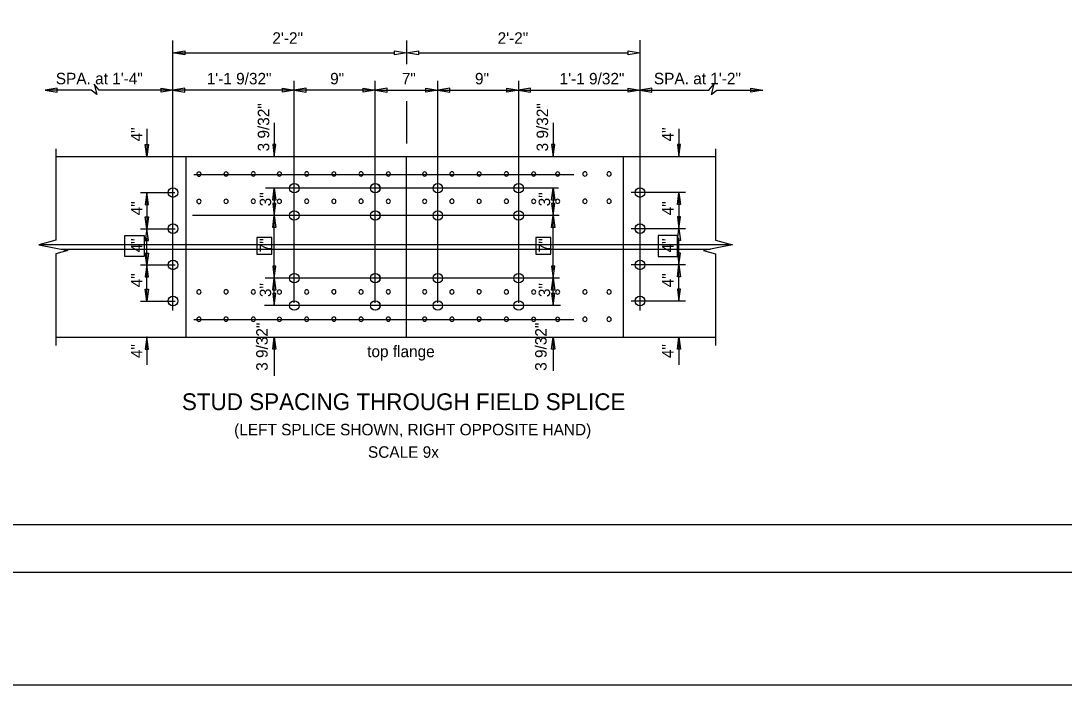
# Model space of a CAD drawing. Extents: x 4944 to 17449, y 3824 to 49087.
# Drawn here: x 13104 to 14149, y 32310 to 32976 of the extents above; entities that cross this region are included whole.
import ezdxf

# ---------------------------------------------------------------- set-up
doc = ezdxf.new("R2010")
doc.units = 0
for name, color, linetype in [('1', 7, 'Continuous'), ('2', 7, 'Continuous'), ('36_S_LINES', 7, 'Continuous'), ('37_S_TXT', 7, 'Continuous'), ('3A', 7, 'Continuous'), ('7', 7, 'Continuous'), ('BEAM', 7, 'Continuous'), ('DIM', 7, 'Continuous'), ('Level 14', 7, 'Continuous'), ('Level 25', 7, 'Continuous'), ('Level 35', 7, 'Continuous')]:
    doc.layers.add(name, color=color, linetype=linetype)

# ---------------------------------------------------------------- blocks, each defined once
blk = doc.blocks.new('4MH')
at = {"layer": 'Level 35'}
for radius, start, end in [(0.0945, 112.5426, 157.4574), (0.06, 112.5426, 157.4574), (0.06, 22.5426, 67.4574), (0.0945, 22.5426, 67.4574), (0.0945, 202.5426, 247.4574), (0.06, 202.5426, 247.4574), (0.06, 292.5426, 337.4574), (0.0945, 292.5426, 337.4574)]:
    blk.add_arc((0, 0), radius, start, end, dxfattribs=at)

msp = doc.modelspace()

# ---------------------------------------------------------------- linework, layer by layer
at = {"layer": '1'}
for centre, start, end in [((13282, 32822.2), 0, 180), ((13282, 32822.2), 180, 0), ((13309.2, 32822.3), 0, 180), ((13309.2, 32822.3), 180, 0), ((13336.5, 32822.4), 0, 180), ((13336.5, 32822.4), 180, 0), ((13362.7, 32822.3), 0, 180), ((13362.7, 32822.3), 180, 0), ((13390, 32822.4), 0, 180), ((13390, 32822.4), 180, 0), ((13417.2, 32822.3), 0, 180), ((13417.2, 32822.3), 180, 0), ((13444.5, 32822.4), 0, 180), ((13444.5, 32822.4), 180, 0), ((13471.8, 32822.3), 0, 180), ((13471.8, 32822.3), 180, 0), ((13508.2, 32822.3), 0, 180), ((13508.2, 32822.3), 180, 0), ((13535.5, 32822.4), 0, 180), ((13535.5, 32822.4), 180, 0), ((13562.8, 32822.3), 0, 180), ((13562.8, 32822.3), 180, 0), ((13590.1, 32822.4), 0, 180), ((13590.1, 32822.4), 180, 0), ((13617.4, 32822.3), 0, 180), ((13617.4, 32822.3), 180, 0), ((13641.5, 32822.3), 0, 180), ((13641.5, 32822.3), 180, 0), ((13668.8, 32822.4), 0, 180), ((13668.8, 32822.4), 180, 0), ((13693, 32822.4), 0, 180), ((13693, 32822.4), 180, 0), ((13282, 32794.8), 0, 180), ((13282, 32794.8), 180, 0), ((13309.2, 32794.9), 0, 180), ((13309.2, 32794.9), 180, 0), ((13336.5, 32795), 0, 180), ((13336.5, 32795), 180, 0), ((13362.7, 32794.9), 0, 180), ((13362.7, 32794.9), 180, 0), ((13390, 32795), 0, 180), ((13390, 32795), 180, 0), ((13417.2, 32794.9), 0, 180), ((13417.2, 32794.9), 180, 0), ((13444.5, 32795), 0, 180), ((13444.5, 32795), 180, 0), ((13471.8, 32794.9), 0, 180), ((13471.8, 32794.9), 180, 0), ((13508.2, 32794.9), 0, 180), ((13508.2, 32794.9), 180, 0), ((13535.5, 32795), 0, 180), ((13535.5, 32795), 180, 0), ((13562.8, 32794.9), 0, 180), ((13562.8, 32794.9), 180, 0), ((13590.1, 32795), 0, 180), ((13590.1, 32795), 180, 0), ((13617.4, 32794.9), 0, 180), ((13617.4, 32794.9), 180, 0), ((13641.5, 32794.9), 0, 180), ((13641.5, 32794.9), 180, 0), ((13668.8, 32795), 0, 180), ((13668.8, 32795), 180, 0), ((13693, 32795), 0, 180), ((13693, 32795), 180, 0), ((13282, 32704.1), 0, 180), ((13282, 32704.1), 180, 0), ((13309.2, 32704.2), 0, 180), ((13309.2, 32704.2), 180, 0), ((13336.5, 32704.1), 0, 180), ((13336.5, 32704.1), 180, 0), ((13362.7, 32704), 0, 180), ((13362.7, 32704), 180, 0), ((13390, 32704.1), 0, 180), ((13390, 32704.1), 180, 0), ((13417.2, 32704.2), 0, 180), ((13417.2, 32704.2), 180, 0), ((13444.5, 32704.1), 0, 180), ((13444.5, 32704.1), 180, 0), ((13471.8, 32704.2), 0, 180), ((13471.8, 32704.2), 180, 0), ((13508.2, 32704.2), 0, 180), ((13508.2, 32704.2), 180, 0), ((13535.5, 32704.1), 0, 180), ((13535.5, 32704.1), 180, 0), ((13562.8, 32704.2), 0, 180), ((13562.8, 32704.2), 180, 0), ((13590.1, 32704.1), 0, 180), ((13590.1, 32704.1), 180, 0), ((13617.4, 32704), 0, 180), ((13617.4, 32704), 180, 0), ((13641.5, 32704), 0, 180), ((13641.5, 32704), 180, 0), ((13668.8, 32704.1), 0, 180), ((13668.8, 32704.1), 180, 0), ((13693, 32704.1), 0, 180), ((13693, 32704.1), 180, 0), ((13282, 32676.7), 0, 180), ((13309.2, 32676.8), 0, 180), ((13336.5, 32676.7), 0, 180), ((13362.7, 32676.6), 0, 180), ((13390, 32676.7), 0, 180), ((13417.2, 32676.8), 0, 180), ((13444.5, 32676.7), 0, 180), ((13471.8, 32676.8), 0, 180), ((13508.2, 32676.8), 0, 180), ((13535.5, 32676.7), 0, 180), ((13562.8, 32676.8), 0, 180), ((13590.1, 32676.7), 0, 180), ((13617.4, 32676.6), 0, 180), ((13641.5, 32676.6), 0, 180), ((13668.8, 32676.7), 0, 180), ((13693, 32676.7), 0, 180), ((13282, 32676.7), 180, 0), ((13309.2, 32676.8), 180, 0), ((13336.5, 32676.7), 180, 0), ((13362.7, 32676.6), 180, 0), ((13390, 32676.7), 180, 0), ((13417.2, 32676.8), 180, 0), ((13444.5, 32676.7), 180, 0), ((13471.8, 32676.8), 180, 0), ((13508.2, 32676.8), 180, 0), ((13535.5, 32676.7), 180, 0), ((13562.8, 32676.8), 180, 0), ((13590.1, 32676.7), 180, 0), ((13617.4, 32676.6), 180, 0), ((13641.5, 32676.6), 180, 0), ((13668.8, 32676.7), 180, 0), ((13693, 32676.7), 180, 0)]:
    msp.add_arc(centre, 2.13, start, end, dxfattribs=at)
at = {"layer": '2'}
msp.add_line((13490, 32658.6), (13490, 32839.9), dxfattribs=at)
at = {"layer": '36_S_LINES'}
for p, q in [((13490, 32956.1), (13490, 32932.3)), ((13256, 32943.9), (13478, 32943.9)), ((13502, 32943.9), (13712, 32943.9)), ((13177.2, 32912.4), (13179.8, 32901.9)), ((13182.1, 32906.5), (13177.2, 32912.4)), ((13793, 32906.5), (13797.8, 32912.4)), ((13797.8, 32912.4), (13795.3, 32901.9)), ((13174, 32906.5), (13127.9, 32906.5)), ((13179.8, 32901.9), (13174, 32906.5)), ((13458.6, 32906.4), (13182.1, 32906.4)), ((13458.6, 32906.4), (13521.5, 32906.4)), ((13521.5, 32906.4), (13792.9, 32906.4)), ((13795.3, 32901.9), (13801, 32906.5)), ((13801, 32906.5), (13847.1, 32906.5)), ((13490, 32895.3), (13490, 32853)), ((13229.8, 32867.6), (13229.8, 32839.9)), ((13357.5, 32873.6), (13357.5, 32839.9)), ((13637, 32873.6), (13637, 32839.9)), ((13763, 32867.6), (13763, 32839.9)), ((13138.7, 32847.5), (13138.7, 32756.1)), ((13799.7, 32847.5), (13799.7, 32756.1)), ((13229.8, 32803.8), (13229.8, 32767.5)), ((13357.5, 32808), (13357.5, 32780.7)), ((13637, 32808), (13637, 32780.7)), ((13763, 32803.8), (13763, 32767.5)), ((13357.5, 32725.9), (13357.5, 32780.8)), ((13637, 32725.9), (13637, 32780.8)), ((13138.7, 32756.1), (13121.6, 32751.3)), ((13229.8, 32731.1), (13229.8, 32758.4)), ((13763, 32731.1), (13763, 32758.4)), ((13799.7, 32756.1), (13816.8, 32751.3)), ((13121.6, 32751.3), (13150.7, 32745.7)), ((13150.7, 32745.7), (13138.7, 32742.3)), ((13138.7, 32742.3), (13138.7, 32650.5)), ((13816.8, 32751.3), (13787.7, 32745.7)), ((13787.7, 32745.7), (13799.7, 32742.3)), ((13799.7, 32742.3), (13799.7, 32650.5)), ((13229.8, 32694.6), (13229.8, 32731.1)), ((13763, 32694.6), (13763, 32731.1)), ((13357.5, 32690.6), (13357.5, 32717.9)), ((13637, 32690.6), (13637, 32717.9)), ((13229.8, 32658.6), (13229.8, 32630.9)), ((13357.5, 32658.6), (13357.5, 32620.1)), ((13637, 32658.6), (13637, 32625.1)), ((13763, 32658.6), (13763, 32630.9))]:
    msp.add_line(p, q, dxfattribs=at)
for points in [[(13268, 32941.9), (13256, 32943.9), (13268, 32945.9)], [(13478, 32945.9), (13490, 32943.9), (13478, 32941.9)], [(13502, 32941.9), (13490, 32943.9), (13502, 32945.9)], [(13712, 32945.9), (13724, 32943.9), (13712, 32941.9)], [(13139.9, 32904.5), (13139.9, 32908.5), (13127.9, 32906.5)], [(13244.1, 32904.5), (13244.1, 32908.5), (13256.1, 32906.5)], [(13267.9, 32904.5), (13267.9, 32908.5), (13255.9, 32906.5)], [(13365.7, 32904.4), (13365.7, 32908.4), (13377.7, 32906.4)], [(13389.4, 32904.4), (13389.4, 32908.4), (13377.4, 32906.4)], [(13446.6, 32904.4), (13446.6, 32908.4), (13458.6, 32906.4)], [(13470.6, 32904.4), (13470.6, 32908.4), (13458.6, 32906.4)], [(13509.5, 32904.4), (13509.5, 32908.4), (13521.5, 32906.4)], [(13533.5, 32904.4), (13533.5, 32908.4), (13521.5, 32906.4)], [(13590.6, 32904.4), (13590.6, 32908.4), (13602.6, 32906.4)], [(13614.3, 32904.4), (13614.3, 32908.4), (13602.3, 32906.4)], [(13712.1, 32904.5), (13712.1, 32908.5), (13724.1, 32906.5)], [(13735.9, 32904.5), (13735.9, 32908.5), (13723.9, 32906.5)], [(13835.1, 32904.5), (13835.1, 32908.5), (13847.1, 32906.5)], [(13228.3, 32851.9), (13231.4, 32851.9), (13229.8, 32839.9)], [(13359, 32851.9), (13356, 32851.9), (13357.5, 32839.9)], [(13638.5, 32851.9), (13635.4, 32851.9), (13637, 32839.9)], [(13764.5, 32851.9), (13761.5, 32851.9), (13763, 32839.9)], [(13359, 32796), (13356, 32796), (13357.5, 32808)], [(13638.5, 32796), (13635.4, 32796), (13637, 32808)], [(13228.3, 32791.7), (13231.4, 32791.7), (13229.8, 32803.7)], [(13764.5, 32791.6), (13761.5, 32791.6), (13763, 32803.6)], [(13359, 32792.7), (13356, 32792.7), (13357.5, 32780.7)], [(13638.5, 32792.7), (13635.4, 32792.7), (13637, 32780.7)], [(13228.3, 32779.5), (13231.4, 32779.5), (13229.8, 32767.5)], [(13359, 32768.8), (13356, 32768.8), (13357.5, 32780.8)], [(13638.5, 32768.8), (13635.4, 32768.8), (13637, 32780.8)], [(13764.5, 32779.5), (13761.5, 32779.5), (13763, 32767.5)], [(13228.3, 32755.5), (13231.4, 32755.5), (13229.8, 32767.5)], [(13764.5, 32755.5), (13761.5, 32755.5), (13763, 32767.5)], [(13228.3, 32743.1), (13231.4, 32743.1), (13229.8, 32731.1)], [(13764.5, 32743.1), (13761.5, 32743.1), (13763, 32731.1)], [(13228.3, 32719.1), (13231.4, 32719.1), (13229.8, 32731.1)], [(13764.5, 32719.1), (13761.5, 32719.1), (13763, 32731.1)], [(13359, 32729.8), (13356, 32729.8), (13357.5, 32717.9)], [(13638.5, 32729.8), (13635.4, 32729.8), (13637, 32717.9)], [(13359, 32705.9), (13356, 32705.9), (13357.5, 32717.9)], [(13638.5, 32705.9), (13635.4, 32705.9), (13637, 32717.9)], [(13228.3, 32706.9), (13231.4, 32706.9), (13229.8, 32694.9)], [(13359, 32702.6), (13356, 32702.6), (13357.5, 32690.6)], [(13638.5, 32702.6), (13635.4, 32702.6), (13637, 32690.6)], [(13764.5, 32706.9), (13761.5, 32706.9), (13763, 32694.9)], [(13228.3, 32646.6), (13231.4, 32646.6), (13229.8, 32658.6)], [(13359, 32646.6), (13356, 32646.6), (13357.5, 32658.6)], [(13638.5, 32646.6), (13635.4, 32646.6), (13637, 32658.6)], [(13764.5, 32646.6), (13761.5, 32646.6), (13763, 32658.6)]]:
    msp.add_lwpolyline(points, close=True, dxfattribs=at)
at = {"layer": '37_S_TXT'}
msp.add_lwpolyline([(12345.1, 34613.8), (15801.2, 34613.8), (15801.2, 32309.8), (12345.1, 32309.8)], close=True, dxfattribs=at)
at = {"layer": '3A'}
for p, q in [((13256, 32685.5), (13256, 32956.1)), ((13724, 32685.5), (13724, 32956.5)), ((13377.6, 32693), (13377.6, 32915.6)), ((13458.6, 32693), (13458.6, 32915.6)), ((13521.5, 32693), (13521.5, 32915.6)), ((13602.5, 32693), (13602.5, 32915.6)), ((13642.2, 32808.1), (13348.7, 32808.1)), ((13223.3, 32803.7), (13258, 32803.7)), ((13769.5, 32803.7), (13715, 32803.7)), ((13643, 32780.7), (13275.5, 32780.7)), ((13223.3, 32767.5), (13258.1, 32767.5)), ((13769.5, 32767.5), (13715, 32767.5)), ((13223.3, 32731.1), (13258.3, 32731.1)), ((13769.5, 32731.1), (13715, 32731.1)), ((13643.4, 32717.9), (13348.4, 32717.9)), ((13223.3, 32694.9), (13258.1, 32694.9)), ((13644.3, 32690.5), (13347.7, 32690.5)), ((13769.5, 32694.9), (13715, 32694.9))]:
    msp.add_line(p, q, dxfattribs=at)
for points in [[(13207.7, 32739.7), (13207.7, 32760.8), (13227.2, 32760.8), (13227.2, 32739.7)], [(13355, 32742.1), (13355, 32758.6), (13340, 32758.6), (13340, 32742.1)], [(13634.5, 32742.1), (13634.5, 32758.6), (13619.5, 32758.6), (13619.5, 32742.1)], [(13761.7, 32739.7), (13761.7, 32760.8), (13742.1, 32760.8), (13742.1, 32739.7)]]:
    msp.add_lwpolyline(points, close=True, dxfattribs=at)
at = {"layer": '7'}
for p, q in [((13122.4, 32751.6), (13815.9, 32751.6)), ((13143.8, 32747), (13794.6, 32747))]:
    msp.add_line(p, q, dxfattribs=at)
at = {"layer": 'DEFPOINTS'}
for p, q in [((13276.8, 32821.9), (13657.6, 32821.9)), ((13276.8, 32676.6), (13657.6, 32676.6))]:
    msp.add_line(p, q, dxfattribs=at)
at = {"layer": 'DIM'}
msp.add_lwpolyline([(12502.3, 34534.6), (15766.4, 34534.6), (15766.4, 32422.6), (12502.3, 32422.6)], close=True, dxfattribs=at)
at = {"layer": 'Level 14'}
msp.add_lwpolyline([(15713.6, 32470.6), (12689.5, 32470.6), (12689.5, 34486.6), (15713.6, 34486.6)], close=True, dxfattribs=at)
at = {"layer": 'Level 25'}
for p, q in [((13138.7, 32839.9), (13799.7, 32839.9)), ((13269.3, 32658.6), (13269.3, 32839.8)), ((13707.6, 32658.6), (13707.6, 32839.9)), ((13138.7, 32658.6), (13799.7, 32658.6))]:
    msp.add_line(p, q, dxfattribs=at)
for centre in [(13256, 32803.7), (13377.6, 32808.1), (13458.6, 32808.1), (13458.8, 32808.1), (13521.4, 32808.1), (13602.4, 32808.1), (13724, 32803.7), (13377.6, 32780.7), (13458.6, 32780.7), (13458.8, 32780.7), (13521.4, 32780.7), (13602.4, 32780.7), (13256, 32767.5), (13724, 32767.5), (13256, 32731.2), (13724, 32731.2), (13377.6, 32717.9), (13458.6, 32717.9), (13458.8, 32717.9), (13521.4, 32717.9), (13602.4, 32717.9), (13256, 32695), (13724, 32695), (13377.6, 32690.5), (13458.6, 32690.5), (13458.8, 32690.5), (13521.4, 32690.5), (13602.4, 32690.5)]:
    msp.add_circle(centre, 4.79, dxfattribs=at)

# ---------------------------------------------------------------- block references
at = {"layer": 'Level 35', "xscale": 5, "yscale": 5}
msp.add_blockref('4MH', (13229.8, 32658.6), dxfattribs=at)

# ---------------------------------------------------------------- texts
at = {"layer": '3A'}
for s, p in [('2\'-2"', (13355.6, 32952.9)), ('2\'-2"', (13581.3, 32952.9)), ('SPA. at 1\'-4"', (13138.6, 32912.3)), ('1\'-1 9/32"', (13289.8, 32912.2)), ('9"', (13413.5, 32912.2)), ('7"', (13485.3, 32912.2)), ('9"', (13558.6, 32912.2)), ('1\'-1 9/32"', (13643.4, 32912.2)), ('SPA. at 1\'-2"', (13737.9, 32912.3)), ('(LEFT SPLICE SHOWN, RIGHT OPPOSITE HAND)', (13317.3, 32560.3))]:
    msp.add_text(s, height=11.52, dxfattribs=at).set_placement(p)
for s, p in [('3 9/32"', (13352.5, 32845)), ('3 9/32"', (13631.9, 32845)), ('4"', (13225.4, 32855)), ('4"', (13757.6, 32855)), ('4"', (13225.4, 32780.9)), ('3"', (13354.4, 32789.9)), ('3"', (13633.9, 32789.9)), ('4"', (13757.6, 32780.9)), ('4"', (13225.4, 32743.7)), ('7"', (13354.4, 32743.8)), ('7"', (13633.9, 32743.8)), ('4"', (13757.6, 32743.7)), ('4"', (13225.4, 32708.7)), ('4"', (13757.6, 32708.7)), ('3"', (13354.4, 32698.9)), ('3"', (13633.9, 32698.9)), ('3 9/32"', (13350.9, 32625)), ('3 9/32"', (13630.4, 32625)), ('4"', (13225.4, 32637.7)), ('4"', (13757.6, 32637.7))]:
    msp.add_text(s, height=11.52, rotation=90, dxfattribs=at).set_placement(p)
at = {"layer": 'BEAM'}
msp.add_text('STUD SPACING THROUGH FIELD SPLICE', height=16.8, dxfattribs=at).set_placement((13265, 32585.6))
at = {"layer": 'DEFPOINTS'}
for s, p in [('top flange', (13450.6, 32638.7)), ('SCALE 9x', (13451.4, 32537.8))]:
    msp.add_text(s, height=11.52, dxfattribs=at).set_placement(p)

doc.saveas('drawing.dxf')
